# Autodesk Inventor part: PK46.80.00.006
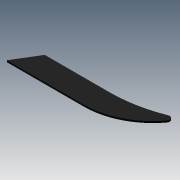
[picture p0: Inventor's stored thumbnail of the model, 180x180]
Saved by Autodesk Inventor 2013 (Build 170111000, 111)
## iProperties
Shininess: 64.0
Length Units: 11269
Angle Units: 11279
Time Units: 11290
Mass Units: 11283
Length Display Precision: 3
Angle Display Precision: 2
Compacted: True
Part Number: PK46.80.00.006
Document SubType Name: Modeling
Created: 2005-01
Material: Steel, Mild
Designer: SAlex
Manufacturer: Standard
Standards Organization: Custom
Density: 7.86 g/cm^3
Mass: 7427.61 g
Surface Area: 2063.9 cm^2
Volume: 944.989 cm^3
Density: 0.0
Volumn: 0.0
Area: 0.0
PropertySet Name: Model Information
Control State: 0
Master: False
Checked Out: False
Checked Out Date: 2008-10-15
Last Check In Date: 2008-10-15
Author: SAlex
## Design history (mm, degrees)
sketch "Sketch1"
  geometry: L1 (0, 0)-(456.881, 0); L2 (468.348, 140)-(85, 140); L3 (85, 140)-(0, 0); A1 r 410 centre (456.881, 410) between (456.881, 0) and (786.057, 165.577); A2 r 20 centre (770, 177.5) between (786.057, 165.577) and (762.643, 196.098); A3 r 800 centre (468.348, 940) between (468.348, 140) and (762.643, 196.098)
  constraints: 6 end point, 6 point on circle, 4 tangent, 3 centre point, 1 horizontal, 1 parallel, 1 other
  dimensions: "d0" = 770 horizontal distance of A2.centre L1.start; "d2" = 20 radius of A2; "d3" = 410 radius of A1; "d4" = 177.5 distance from line of A2.centre L1; "d5" = 800 radius of A3; "d6" = 85 horizontal distance of L2.end L1.start; "d7" = 140 distance between parallel lines of L2 L1
extrude "Extrusion1" new body sketch "Sketch1" distance "d8" = 10; taper "d9" = 0 deg
body "Solid1"
